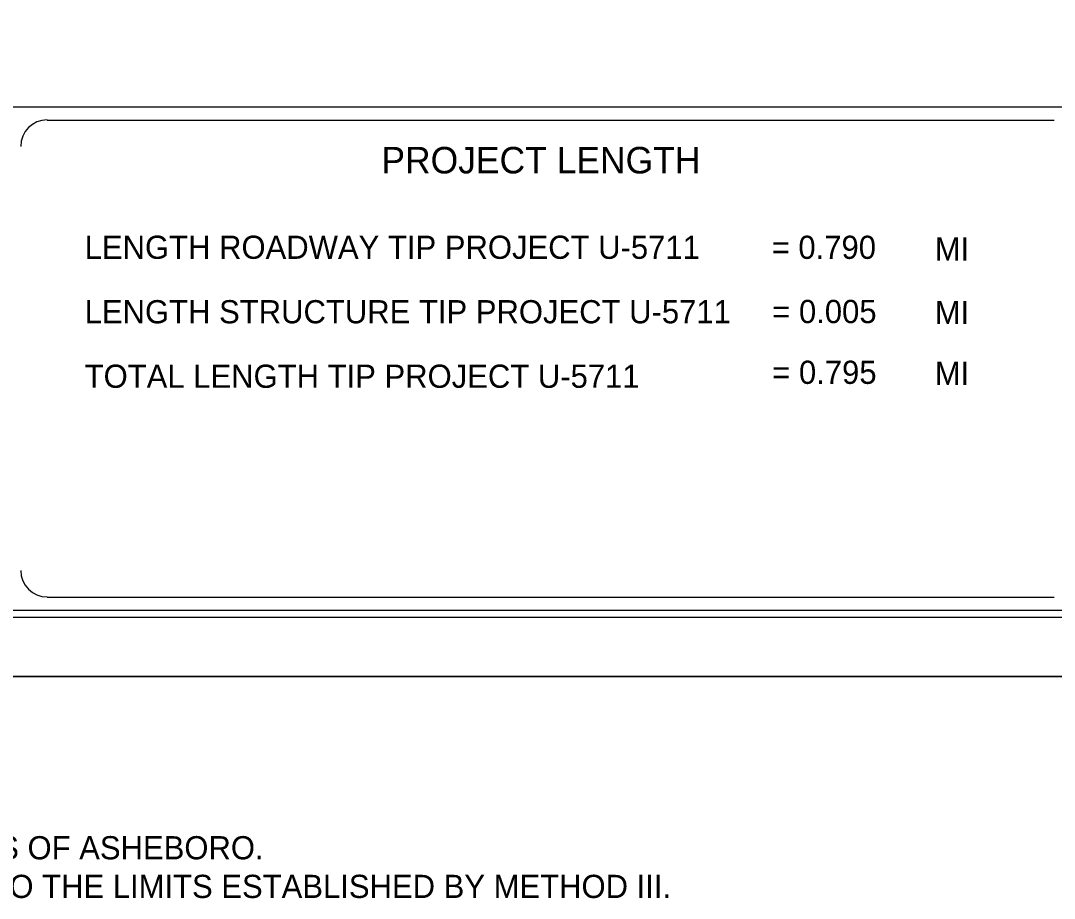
# Model space of a CAD drawing. Extents: x 1750553 to 1763838, y 734059 to 742526.
# Drawn here: x 1755472 to 1757812, y 734059 to 736046 of the extents above; entities that cross this region are included whole.
import ezdxf

# ---------------------------------------------------------------- set-up
doc = ezdxf.new("R2010")
doc.units = 0
for name, color, linetype in [('Scratch_Level_3', 7, 'Continuous'), ('Sheet Cutting Line CELL', 7, 'Continuous'), ('Sheet PE Seal Cell', 7, 'Continuous'), ('Sheet Plot Border Inside CELL', 7, 'Continuous'), ('Sheet Plot Border Outside CELL', 7, 'Continuous'), ('Sheet Title CELL', 7, 'Continuous')]:
    doc.layers.add(name, color=color, linetype=linetype)

msp = doc.modelspace()

# ---------------------------------------------------------------- linework, layer by layer
at = {"layer": 'Sheet Cutting Line CELL'}
for p, q in [((1752099.6, 734560.9), (1762203.6, 734560.9)), ((1762200.6, 734560.9), (1752099.6, 734560.9))]:
    msp.add_line(p, q, dxfattribs=at)
at = {"layer": 'Sheet Plot Border Inside CELL'}
msp.add_lwpolyline([(1752177.6, 734695.6), (1762176.6, 734695.6), (1762176.6, 741026.2), (1752177.6, 741026.2)], close=True, dxfattribs=at)
at = {"layer": 'Sheet Plot Border Outside CELL'}
msp.add_lwpolyline([(1762203.6, 741160.9), (1752099.6, 741160.9), (1752099.6, 734560.9), (1762203.6, 734560.9)], close=True, dxfattribs=at)
at = {"layer": 'Sheet Title CELL'}
for p, q in [((1753491.6, 735850.9), (1762011.6, 735850.9)), ((1755531.6, 735820.9), (1757811.6, 735820.9))]:
    msp.add_line(p, q, dxfattribs=at)
for points in [[(1755531.6, 734740.9), (1757811.6, 734740.9)], [(1753161.6, 734710.9), (1762041.6, 734710.9)]]:
    msp.add_lwpolyline(points, dxfattribs=at)
for centre, start, end in [((1755531.6, 735761.2), 90, 180), ((1755531.6, 734801.2), 180, 270)]:
    msp.add_arc(centre, 60, start, end, dxfattribs=at)

# ---------------------------------------------------------------- texts
at = {"layer": 'Scratch_Level_3'}
for s, height, p in [('= 0.790', 52.5, (1757171.7, 735506.5)), ('MI', 52.5, (1757541, 735502.8)), ('= 0.005', 52.5, (1757173, 735361.1)), ('MI', 52.5, (1757541, 735358.9)), ('= 0.795', 52.5, (1757173, 735223.5)), ('MI', 52.5, (1757541, 735221.3)), ('THIS PROJECT IS WITHIN THE MUNICIPAL BOUNDARIES OF ASHEBORO.', 52.501, (1753560.2, 734147)), ('CLEARING ON THIS PROJECT SHALL BE PERFORMED TO THE LIMITS ESTABLISHED BY METHOD III.', 52.501, (1753550.2, 734059.5))]:
    msp.add_text(s, height=height, rotation=0.0001, dxfattribs=at).set_placement(p)
at = {"layer": 'Sheet PE Seal Cell'}
for s, p in [('LENGTH ROADWAY TIP PROJECT U-5711', (1755616.5, 735506.6)), ('LENGTH STRUCTURE TIP PROJECT U-5711', (1755616.5, 735360.6)), ('TOTAL LENGTH TIP PROJECT U-5711', (1755616.5, 735214.6))]:
    msp.add_text(s, height=52.501, rotation=0.0001, dxfattribs=at).set_placement(p)
at = {"layer": 'Sheet Title CELL'}
msp.add_text('PROJECT LENGTH', height=59.998, rotation=360, dxfattribs=at).set_placement((1756288.2, 735700))

doc.saveas('drawing.dxf')
